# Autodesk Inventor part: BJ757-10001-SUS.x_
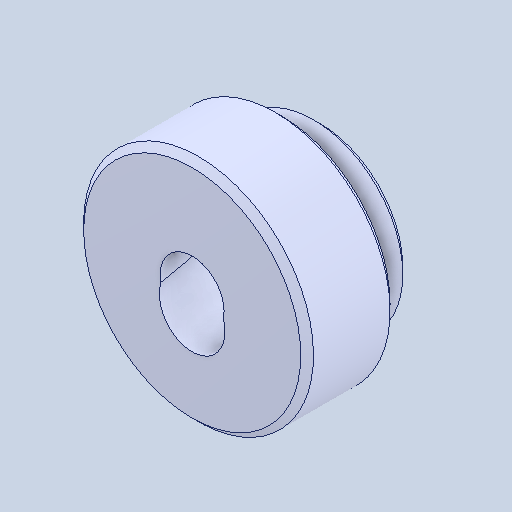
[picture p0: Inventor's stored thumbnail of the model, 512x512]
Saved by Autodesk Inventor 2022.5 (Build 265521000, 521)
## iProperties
Created: 2024-05
Part Number: BJ757-10001-SUS.x_
Material: 一般
Document SubType Name: Modeling
Designer: ImaoCorp
Density: 1 g/cm^3
Appearance: 既定
Author: ImaoCorp
Sending System: SOLIDWORKS 2022-2022290
MC: AMD64
MC_MODEL: Intel64 Family 6 Model 60 Stepping 3, GenuineIntel
OS: Windows_NT
FRU: Parasolid Version 33.1, build 260,  4-25-2022
FORMAT: text
GUISE: transmit
KEY: FILEBJ757-10001-SUS.x_t
DATE: Tue May 21 08:47:07 2024
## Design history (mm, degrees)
feature "Base1"
node "ソリッド1"
